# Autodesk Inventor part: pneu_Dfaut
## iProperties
Created: 2006-03
Part Number: pneu_Dfaut
Document SubType Name: Modeling
Designer: Flavien MARTY
Author: Flavien MARTY
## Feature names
1. Base1
2. Révolution1 [Revolution]
